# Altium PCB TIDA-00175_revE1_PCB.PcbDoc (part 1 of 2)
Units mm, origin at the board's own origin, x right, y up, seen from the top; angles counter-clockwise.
Board outline 109.99 x 49.78 mm, 4 copper layers (Top Layer, mid layer 1-GND, mid layer 2-VCC, Bottom Layer), stack 2.286 mm thick; 124 components, 74 nets, 385 pads, 135 vias.
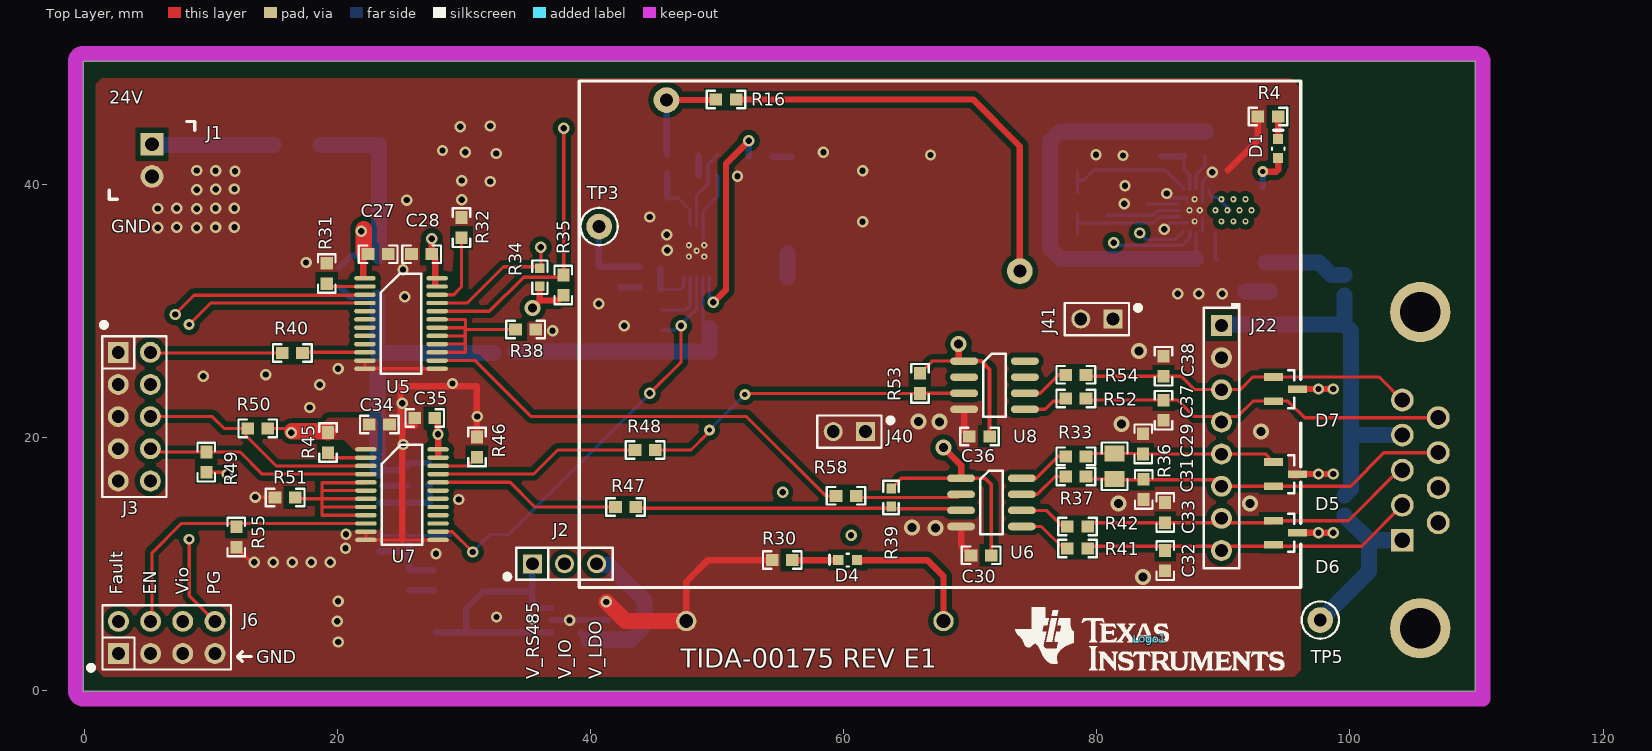
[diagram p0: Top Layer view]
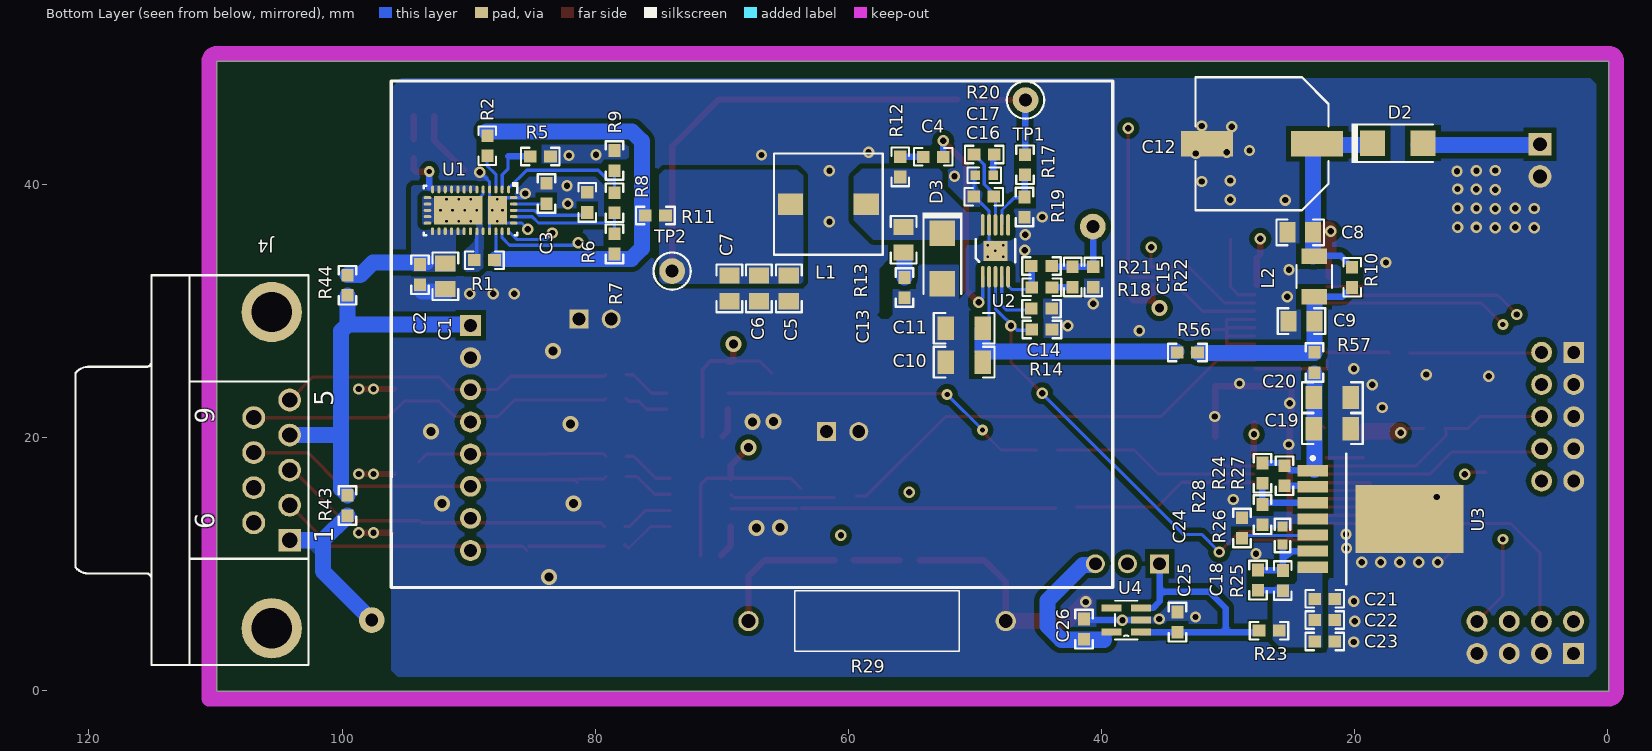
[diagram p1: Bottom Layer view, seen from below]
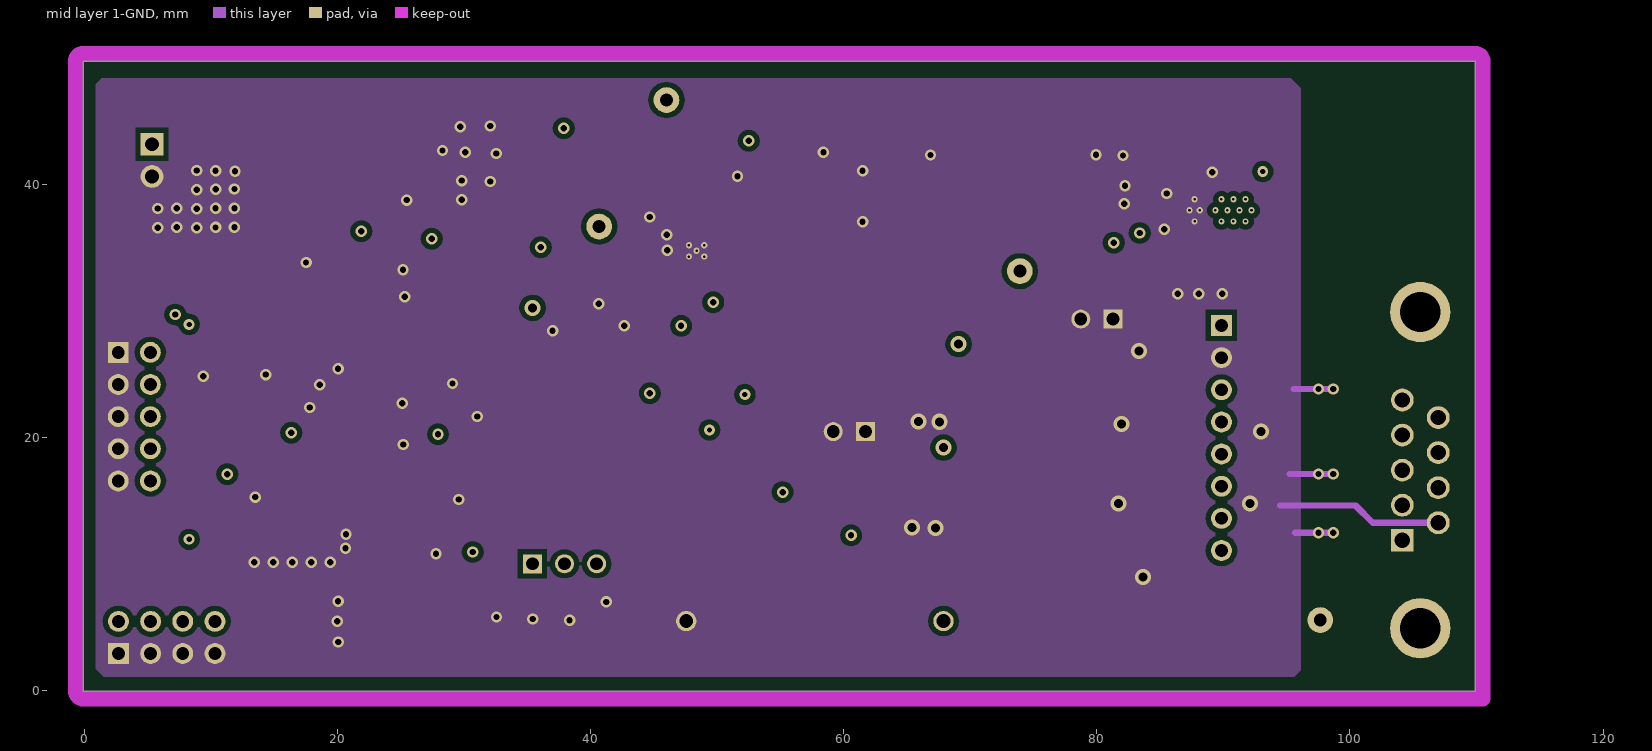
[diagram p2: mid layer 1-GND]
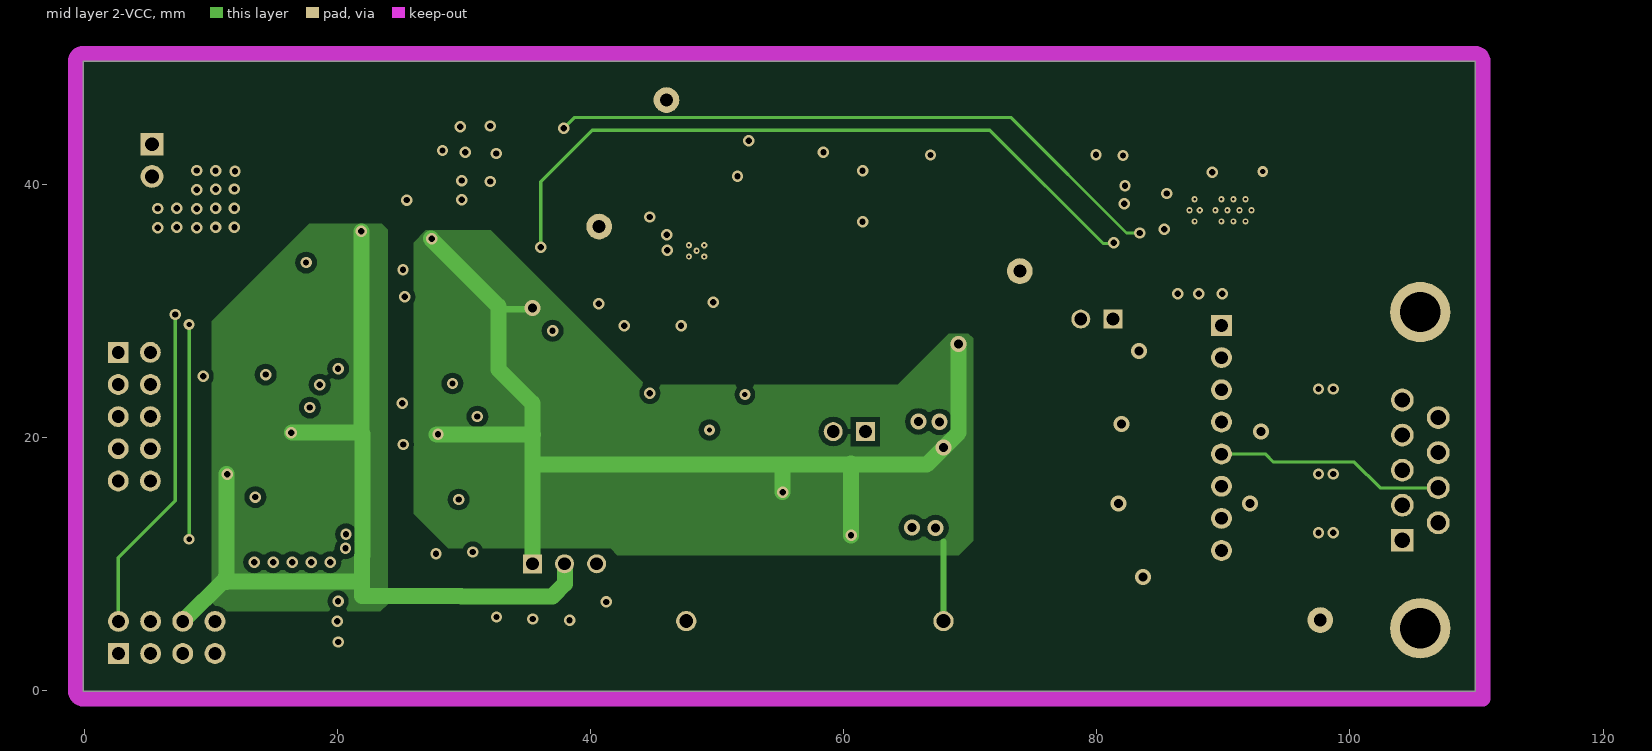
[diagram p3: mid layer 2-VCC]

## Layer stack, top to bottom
Top Layer: signal copper 0.0356
Dielectric: prepreg 1.5037, FR-4, Dk 4.8
mid layer 1-GND: signal copper 0.0356
Dielectric: core 0.32, FR-4, Dk 4.8
mid layer 2-VCC: signal copper 0.0356
Dielectric: prepreg 0.32, FR-4, Dk 4.8
Bottom Layer: signal copper 0.0356

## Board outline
-0.079,-0.068 -0.077,49.714 109.916,49.714 109.916,-0.068

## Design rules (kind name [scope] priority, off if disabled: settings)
AcuteAngle [All] p1: minimum=4.50000000000000E+0001 checktracksonly=FALSE
AssemblyTestPointUsage [All] p1: valid=2
Clearance Clearance_BoardEdge_MountingHoles [OnCopper and InComponentClass('Mounting Holes') vs IsKeepOut] p1: gap=1.016
Clearance Clearance_BoardEdge_Poly [OnCopper and InPoly vs IsKeepOut] p2: gap=0.635
Clearance Clearance_BoardEdge [OnCopper and Not InComponentClass('Logo') and not InComponentClass('FiducialMark') and not InRegion(1000,500,4000,800) and Not IsKeepout vs IsKeepOut] p3: gap=1.905
Clearance Clearance_Poly [InPolygon] p4: gap=0.4
Clearance Clearance_U2 [(ObjectKind = 'Pad') And (Component = 'U2') vs (ObjectKind = 'Pad') And (Component = 'U2')] p5: gap=0.198
Clearance [All] p6: gap=0.203
ComponentClearance ComponentClearance_Shunt [InComponentClass('Header') vs InComponentClass('Shunt')] p1: gap=0 collisioncheckmode=3 verticalgap=0 showdistances=FALSE
ComponentClearance ComponentClearance_Logo [InComponentClass('Logo')] p2: gap=1.27 collisioncheckmode=3 verticalgap=0.254 showdistances=FALSE
ComponentClearance ComponentClearance_ScrewToNut [(HasFootprint('NY PMS 440 0025 PH')) vs (HasFootprint('Keystone_1902C'))] p3: gap=0.127 collisioncheckmode=3 verticalgap=0.254 showdistances=FALSE
ComponentClearance ComponentClearance_MountingHoles [InComponentClass('Mounting Holes')] p4: gap=6.35 collisioncheckmode=3 verticalgap=2540 showdistances=FALSE
ComponentClearance ComponentClearance_SmallPassives [HasFootprint('0201*') or HasFootprint('0402*') or HasFootprint('0508') or HasFootprint('0603*') or HasFootprint('0612') or HasFootprint('0805*') or HasFootprint('0815*') or HasFootprint('0830*') or HasFootprint('1206*') or HasFootprint('1210*') or HasFootprint('1808*') or HasFootprint('1812*') or HasFootprint('1825*') or HasFootprint('2010*') or HasFootprint('2220*') or HasFootprint('2225*') or HasFootprint('2512*') or HasFootprint('2728*') or HasFootprint('3518*') vs HasFootprint('0201*') or HasFootprint('0402*') or HasFootprint('0508') or HasFootprint('0603*') or HasFootprint('0612') or HasFootprint('0805*') or HasFootprint('0815*') or HasFootprint('0830*') or HasFootprint('1206*') or HasFootprint('1210*') or HasFootprint('1808*') or HasFootprint('1812*') or HasFootprint('1825*') or HasFootprint('2010*') or HasFootprint('2220*') or HasFootprint('2225*') or HasFootprint('2512*') or HasFootprint('2728*') or HasFootprint('3518*')] p5: gap=0.508 collisioncheckmode=3 verticalgap=0.254 showdistances=FALSE
ComponentClearance ComponentClearance_THtoSMT [IsThruComponent vs IsSMTComponent] p6: gap=2.54 collisioncheckmode=3 verticalgap=0.762 showdistances=FALSE
ComponentClearance ComponentClearance_THtoTH [IsThruComponent vs IsThruComponent] p7: gap=3 collisioncheckmode=3 verticalgap=0.762 showdistances=FALSE
ComponentClearance [All] p8: gap=1.016 collisioncheckmode=3 verticalgap=0.254 showdistances=FALSE
DiffPairsRouting [All] p1: maxlimit=2.54 minlimit=0.254 mostfreqgap=0.254 maxuncoupledlength=25.4
FabricationTestPointUsage TestPointUsage [All] p1: valid=2 allowmultiple=FALSE
FabricationTestpoint Testpoint [All] p1: side=3 testpointundercomponent=TRUE minsize=1.016 maxsize=2.54 preferedsize=1.524 minholesize=0 maxholesize=1.016 preferedholesize=0.813 testpointgrid=0.025 allowsidetop=TRUE allowsidebottom=TRUE usegrid=TRUE gridtolerance=0
FanoutControl Fanout_LCC [IsLCC] p1: bgadir=Out bgaviamode=Centered fanoutstyle=Auto fanoutdirection=Alternating viagrid=0.025 // Fanout_LCC (Default Rule)
FanoutControl Fanout_BGA [IsBGA] p2: bgadir=Out bgaviamode=Centered fanoutstyle=Auto fanoutdirection=Alternating viagrid=0.025 // Fanout_BGA (Default Rule)
FanoutControl Fanout_Default [All] p4: bgadir=Out bgaviamode=Centered fanoutstyle=Auto fanoutdirection=Alternating viagrid=0.025 // Fanout_Default (Default Rule)
FanoutControl Fanout_Small [(CompPinCount < 5)] p5: bgadir=Out bgaviamode=Centered fanoutstyle=Auto fanoutdirection=OutThenIn viagrid=0.025 // Fanout_Small (Default Rule)
HoleSize HoleSize_CompoentPAD [((Component = U2) or (Component =U1)) and isVia] p1: absolutevalues=TRUE maxlimit=6.375 minlimit=0.2 maxpercent=80.000 minpercent=20.000
HoleSize [All] p2: absolutevalues=TRUE maxlimit=6.375 minlimit=0.203 maxpercent=80.000 minpercent=20.000
MinimumAnnularRing MinimumAnnularRing_ThermalPadVias_U1 [IsVia and (Component = U1)] p1: minimumring=0.099
MinimumAnnularRing MinimumAnnularRing_ThermalPadVias_U2 [IsVia and (Component = U2)] p2: minimumring=0.099
MinimumAnnularRing MinimumAnnularRing_ThermalPadVias [IsVia and InAnyComponent] p3: minimumring=0.15
MinimumAnnularRing [All] p4: minimumring=0.2
MinimumSolderMaskSliver MinimumSolderMaskSliver_ComponentPAD [Component = U2 vs Component = U2] p1: minsoldermaskwidth=0.045
MinimumSolderMaskSliver MinimumSolderMaskSliver_Logo [InComponentClass('Logo') vs InComponentClass('Logo')] p2: minsoldermaskwidth=0.018
MinimumSolderMaskSliver [All] p3: minsoldermaskwidth=0.1
PlaneConnect [All] p1: planeconnectstyle=Relief reliefexpansion=0.254 reliefentries=4 reliefconductorwidth=0.254 reliefairgap=0.254
PolygonConnect [All] p1: connectstyle=Direct reliefconductorwidth=0.254 reliefentries=4 polygonreliefangle="90 Angle" airgapwidth=0.254
RoutingVias ComponentPadVias [IsVia and ((Component = U2) or (Component = U1))] p1: holewidth=0.2 width=0.2 viastyle="Through Hole" minholewidth=0.199 minwidth=0.199 maxholewidth=0.33 maxwidth=0.6
RoutingVias ThermalPadVias [IsVia and InAnyComponent] p2: holewidth=0.2 width=0.5 viastyle="Through Hole" minholewidth=0.3 minwidth=0.5 maxholewidth=0.33 maxwidth=0.6
RoutingVias [All] p3: holewidth=0.406 width=0.864 viastyle="Through Hole" minholewidth=0.3 minwidth=0.66 maxholewidth=1.016 maxwidth=1.651
SMDToCorner SMDToCorner_TPS24750 [InNet(NetR1_1)] p1: distance=18000
SMDToCorner [All] p2: distance=30000
SilkToSilkClearance [All] p1: silktosilkclearance=0.127
SilkscreenOverComponentPads [All] p1: minsilkscreentomaskgap=0.127
SolderMaskExpansion [All] p1: expansion=0.05
Width [All] p1: maxlimit=2.54 minlimit=0.152 preferedwidth=0.254 checkconnectedcopper=TRUE
14 further rules are at their usual default settings.

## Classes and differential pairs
component class Header: J22
component class TIDA-00175_revE1_Block_Diagram: Logo1
component class Logo: Logo1
component class TIDA-00175_revE1_PR: C1 C2 C3 D1 R1 R2 R4 R5 R6 R7 R8 R9 U1
component class TIDA-00175_revE1_PS: C4 C5 C6 C7 C8 C9 C10 C11 C12 C13 C14 C15 C16 C17 C18 C19 C20 C21 C22 C23 C24 C25 C26 D2 D3 D4 J1 J2 L1 L2 R10 R11 R12 R13 R14 R16 R17 R18 R19 R20 R21 R22 R23 R24 R25 R26 R27 R28 R29 R30 R56 R57 TP1 TP2 TP3 U2 U3 U4
component class TIDA-00175_revE1_SC: C27 C28 C29 C30 C31 C32 C33 C34 C35 C36 C37 C38 C43 D5 D6 D7 J3 J4 J6 J22 J40 J41 R31 R32 R33 R34 R35 R36 R37 R38 R39 R40 R41 R42 R43 R44 R45 R46 R47 R48 R49 R50 R51 R52 R53 R54 R55 R58 R63 R73 R74 R76 TP5 U5 U6 U7 U8

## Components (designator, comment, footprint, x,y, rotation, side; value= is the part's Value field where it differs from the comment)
C1 "C2012X5R1E106K125AB" 0805_HV 91.849,32.719 r270 bottom
C2 "C1608X7R1E104K" 0603 93.857,32.842 r270 bottom
C3 "GRM188R71H333KA61D" 0603 83.863,39.26 r270 bottom
C4 "GRM188R61C104KA01D" 0603 53.3,42.153 r0 bottom
C5 "C2012X5R1E106K125AB" 0805_HV 64.706,31.761 r270 bottom
C6 "C2012X5R1E106K125AB" 0805_HV 67.069,31.761 r270 bottom
C7 "C2012X5R1E106K125AB" 0805_HV 69.405,31.761 r270 bottom
C8 "GRM21BR71H105KA12L" 0805_HV 24.304,36.19 r0 bottom
C9 "GRM21BR71H105KA12L" 0805_HV 24.21,29.17 r0 bottom
C10 "GRM31CR61H225KA88L" 1206 50.854,25.936 r0 bottom
C11 "GRM31CR61H225KA88L" 1206 50.854,28.611 r0 bottom
C12 "EEE-FK1J101P" SM_RADIAL_G 27.323,43.186 r0 bottom
C13 "GRM188R60J106ME47D" 0603 55.562,31.825 r270 bottom
C14 "GRM188R71C222KA01D" 0603 44.746,30.155 r180 bottom
C15 "C1608C0G1H100D" 0603 42.283,32.661 r90 bottom
C16 "GRM1885C1H120JA01D" 0603 49.307,39.005 r0 bottom
C17 "GRM188R71H123KA01D" 0603_HV 49.273,40.692 r0 bottom
C18 "GRM188R71C223KA01D" 0603 27.643,8.711 r90 bottom
C19 "GRM31CR61H225KA88L" 1206 21.772,20.668 r180 bottom
C20 "GRM31CR61H225KA88L" 1206 21.771,23.137 r180 bottom
C21 "C1608X5R1A106M" 0603 22.368,7.235 r180 bottom
C22 "C1608X5R1A106M" 0603 22.368,5.551 r180 bottom
C23 "C1608X5R1A106M" 0603 22.368,3.868 r180 bottom
C24 "GRM188R71C333KA01D" 0603 28.898,12.828 r90 bottom
C25 "GRM188R61C104KA01D" 0603 34.004,5.394 r90 bottom
C26 "GRM188R61C104KA01D" 0603 41.386,4.837 r90 bottom
C27 "06033D104KAT2A" 0603 23.226,34.46 r180 top
C28 "06033D104KAT2A" 0603 26.661,34.461 r180 top
C29 "GRM188R71H221KA01D" 0603 83.671,19.475 r270 top
C30 "06033D104KAT2A" 0603 70.866,10.668 r0 top
C31 "GRM188R71H221KA01D" 0603 83.705,15.875 r270 top
C32 "GRM188R71H221KA01D" 0603 85.408,10.25 r90 top
C33 "GRM188R71H221KA01D" 0603 85.408,14.05 r90 top
C34 "06033D104KAT2A" 0603 23.324,21.015 r180 top
C35 "06033D104KAT2A" 0603 26.914,21.515 r180 top
C36 "06033D104KAT2A" 0603 70.739,20.066 r0 top
C37 "GRM188R71H221KA01D" 0603 85.281,22.134 r90 top
C38 "GRM188R71H221KA01D" 0603 85.281,25.611 r90 top
D1 "LG L29K-G2J1-24-Z" "LG L29K_GREEN" 94.335,42.799 r90 top
D2 "MBRA160T3G" SMA 16.602,43.23 r180 bottom
D3 "MBRA160T3G" SMA 52.575,34.114 r270 bottom
D4 "LG L29K-G2J1-24-Z" "LG L29K_GREEN" 60.325,10.296 r180 top
D5 "CDSOT23-SM712" SOT-23 94.917,17.09 r0 top
D6 "CDSOT23-SM712" SOT-23 94.917,12.458 r0 top
D7 "CDSOT23-SM712" SOT-23 94.917,23.807 r0 top
J1 "1725656" CONN_1725656 5.36,41.876 r270 top
J2 "PEC03SAAN" CONN_PEC03SAAN 37.952,10 r0 top
J3 "PEC05DAAN" CONN_PEC05DAAN 3.963,21.628 r270 top
J4 "1734348-1" CONN_1734348-1 115.062,17.399 r90 bottom
J6 "PEC04DAAN" CONN_PEC04DAAN 6.523,4.183 r0 top
J22 "PEC08SAAN" SULLINS_PEC08SAAN 89.854,19.939 r270 top
J40 "PEC02SAAN" CONN_PEC02SAAN 60.452,20.447 r180 top
J41 "PEC02SAAN" CONN_PEC02SAAN 80.01,29.337 r180 top
L1 "7447779182" WE-PD-M 61.582,38.42 r0 bottom
L2 "NLCV32T-4R7M-PFR" NLCV32 23.207,32.694 r270 bottom
Logo1 "Texas Instruments" TI_Stacked_Overlay_Small 84.201,4.064 r0 top
R1 "ERJ-L03KF50MV" 0603 88.762,33.986 r180 bottom
R2 "CRCW060350R0FKEA" 0603 88.528,43.027 r90 bottom
R4 "CRCW06031K00JNEA" 0603 93.535,45.345 r0 top
R5 "CRCW06031K69FKEA" 0603 84.341,42.172 r0 bottom
R6 "CRCW06034K99FKEA" 0603 80.634,38.558 r270 bottom
R7 "CRCW060393K1FKEA" 0603 78.477,35.274 r270 bottom
R8 "CRCW060320K5FKEA" 0603 78.475,38.525 r270 bottom
R9 "RC0603FR-0730KL" 0603 78.475,41.86 r270 bottom
R10 "CRCW060310R0JNEAHP" 0603 20.197,32.636 r270 bottom
R11 "CRCW06030000Z0EA" 0603 75.253,37.524 r0 bottom
R12 "CRCW06030000Z0EA" 0603 55.905,41.358 r270 bottom
R13 "CRCW080510K0JNEA" 0805_HV 55.64,35.597 r90 bottom
R14 "CRCW06034K70JNEA" 0603 44.717,28.502 r180 bottom
R16 "CRCW060351R0JNEA" 0603 50.708,46.689 r180 top
R17 "CRCW060354K9FKEA" 0603 46.04,41.529 r90 bottom
R18 "CRCW06033K90JNEA" 0603 44.715,31.847 r0 bottom
R19 "CRCW060310K0FKEA" 0603 46.093,38.185 r90 bottom
R20 "CRCW060338K3FKEA" 0603 49.273,42.343 r0 bottom
R21 "CRCW0603165KFKEA" 0603 44.748,33.522 r0 bottom
R22 "CRCW060351R0JNEA" 0603 40.658,32.662 r90 bottom
R23 "CRCW06030000Z0EA" 0603 26.767,4.713 r0 bottom
R24 "CRCW060390K9FKEA" 0603 27.28,17.158 r90 bottom
R25 "CRCW060315K4FKEA" 0603 25.679,8.674 r270 bottom
R26 "CRCW06034K99FKEA" 0603_HV 25.708,12.242 r270 bottom
R27 "CRCW060336K5FKEA" 0603 25.551,16.958 r270 bottom
R28 "CRCW060310K0FKEA" 0603 27.293,13.887 r90 bottom
R29 "AC03000001009JAC00" RESAD2032W80L1300D480 57.732,5.473 r0 bottom
R30 "CRCW0603390RJNEA" 0603 55.155,10.296 r0 top
R31 "CRCW06034K70JNEA" 0603 19.168,32.937 r270 top
R32 "CRCW06034K70JNEA" 0603 29.814,36.561 r90 top
R33 "CRCW060310R0JNEAHP" 0603 78.353,18.493 r0 top
R34 "CRCW06034K70JNEA" 0603_HV 36.009,32.644 r90 top
R35 "CRCW06034K70JNEA" 0603 37.854,32.022 r270 top
R36 "ERJ-P06J121V" 0805_HV 81.407,17.705 r90 top
R37 "CRCW060310R0JNEAHP" 0603 78.353,16.889 r0 top
R38 "CRCW06034K70JNEA" 0603 34.878,28.508 r180 top
R39 "CRCW06034K70JNEA" 0603_HV 63.754,15.24 r270 top
R40 "CRCW060322R0JNEA" 0603 16.454,26.652 r0 top
R41 "CRCW060310R0JNEAHP" 0603 78.48,11.207 r0 top
R42 "CRCW060310R0JNEAHP" 0603 78.48,12.951 r0 top
R43 "CRCW06030000Z0EA" 0603 99.568,14.605 r270 bottom
R44 "CRCW06030000Z0EA" 0603 99.568,32.004 r270 bottom
R45 "CRCW06034K70JNEA" 0603 19.27,19.577 r90 top
R46 "CRCW06034K70JNEA" 0603 31.03,19.221 r270 top
R47 "CRCW060322R0JNEA" 0603 42.776,14.487 r0 top
R48 "CRCW060322R0JNEA" 0603 44.323,18.993 r0 top
R49 "CRCW06034K70JNEA" 0603 9.652,18.034 r90 top
R50 "CRCW06034K70JNEA" 0603 13.716,20.701 r180 top
R51 "CRCW06034K70JNEA" 0603 15.882,15.234 r180 top
R52 "CRCW060310R0JNEAHP" 0603 78.353,23.058 r0 top
R53 "CRCW06034K70JNEA" 0603 66.04,24.257 r270 top
R54 "CRCW060310R0JNEAHP" 0603 78.353,24.931 r0 top
R55 "CRCW06034K70JNEA" 0603 12.021,12.116 r90 top
R56 "CRCW06030000Z0EA" 0603 33.22,26.693 r0 bottom
R57 "CRCW06030000Z0EA" 0603 23.168,25.908 r90 bottom
R58 "CRCW060322R0JNEA" 0603 60.198,15.367 r0 top
TP1 "5000" Keystone5000 46.009,46.641 r90 bottom
TP2 "5000" Keystone5000 73.927,33.125 r90 bottom
TP3 "5002" Keystone5002 40.69,36.647 r0 top
TP5 "5000" Keystone5000 97.663,5.559 r0 top
U1 "TPS24750RUV" RUV0036A 89.854,37.923 r270 bottom
U2 "TPS54040ADGQ" DGQ0010D_N 48.384,34.723 r90 bottom
U3 "LMZ14201TZ-ADJ/NOPB" TZA07A_V 17.963,13.545 r180 bottom
U4 "TLV70025DDC" DDC0005A_N 38.052,5.559 r0 bottom
U5 "SN74AVC8T245PW" PW0024A_N 25.035,28.983 r0 top
U6 "SN65HVD77D" D0008A_N 71.685,14.853 r0 top
U7 "SN74AVC8T245PW" PW0024A_N 25.112,15.462 r0 top
U8 "SN65HVD77D" D0008A_N 71.924,24.11 r0 top

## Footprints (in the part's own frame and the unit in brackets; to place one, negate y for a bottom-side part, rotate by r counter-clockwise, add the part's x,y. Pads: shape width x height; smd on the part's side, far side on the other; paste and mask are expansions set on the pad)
0603 [mm] "0603 from SM-752 data"
  rect 1x0.95 smd: 1(-0.8,0) 2(0.8,0)
  silkscreen extent -1.52,-0.69 1.52,0.69, body extent -0.87,-0.47 0.87,0.47, height 0.85
0603_HV [mil] "Ernesto recommended land pattern.  26 mil between pads."
  rect 30x30 smd: 1(-28,0) 2(28,0)
  silkscreen extent -52,-24 52,24, body extent -34,-19 34,19, height 33
0805_HV [mil] "0805 with 30mil clearance between pads"
  rect 50x63 smd: 1(-40,0) 2(40,0)
  silkscreen extent -74,-40 74,40, body extent -43,-29 43,29, height 43
1206 [mm] "1206 from SM-752 data"
  rect 1.3x1.85 smd: 1(-1.45,0) 2(1.45,0)
  silkscreen extent -2.4,-1.21 2.4,1.21, body extent -1.7,-0.9 1.7,0.9, height 1.35
CONN_1725656 [mm] "Phoenix Contact"
  rect 1.8x1.8 hole 1.1: 1(-1.27,0)
  round 1.8 hole 1.1: 2(1.27,0)
  silkscreen extent -3.08,-3.37 3.08,3.37, body extent -2.77,-3.1 2.77,3.1, height 8.52
CONN_1734348-1 [mm] "Connector; D Subminiature 9 Position; Right Angle"
  rect 1.8x1.8 hole 1.2: 1(-5.54,-10.92)
  round 1.8 hole 1.2: 2(-2.77,-10.92) 3(0,-10.92) 4(2.77,-10.92) 5(5.54,-10.92) 6(-4.155,-8.08) 7(-1.385,-8.08) 8(1.385,-8.08) 9(4.155,-8.08)
  round 4.76 hole 3.18: 10(-12.495,-9.5) 11(12.495,-9.5)
  silkscreen extent -15.4,-12.4 15.4,6, body extent -15.4,-12.4 15.4,6.02, height 12.52
CONN_PEC02SAAN [mm] "SULLINS"
  rect 1.5x1.5 hole 1.016: 1(-1.27,0)
  round 1.5 hole 1.016: 2(1.27,0)
  silkscreen extent -3.45,-1.27 2.54,1.27, body extent -2.54,-1.27 2.54,1.27, height 8.38
CONN_PEC03SAAN [mm] "SULLINS"
  rect 1.5x1.5 hole 1.016: 1(-2.54,0)
  round 1.5 hole 1.016: 2(0,0) 3(2.54,0)
  silkscreen extent -4.72,-1.27 3.81,1.27, body extent -3.84,-1.3 3.84,1.3, height 8.38
CONN_PEC04DAAN [mm] "SULLINS"
  rect 1.65x1.65 hole 1.016 mask+0: 1(-3.81,-1.27)
  round 1.65 hole 1.016 mask+0: 2(-3.81,1.27) 3(-1.27,-1.27) 4(-1.27,1.27) 5(1.27,-1.27) 6(1.27,1.27) 7(3.81,-1.27) 8(3.81,1.27)
  silkscreen extent -6.18,-2.6 5.08,2.54, body extent -5.08,-2.54 5.08,2.54, height 8.38
CONN_PEC05DAAN [mm] "SULLINS"
  rect 1.65x1.65 hole 1.016 mask+0: 1(-5.08,-1.27)
  round 1.65 hole 1.016 mask+0: 2(-5.08,1.27) 3(-2.54,-1.27) 4(-2.54,1.27) 5(0,-1.27) 6(0,1.27) 7(2.54,-1.27) 8(2.54,1.27) 9(5.08,-1.27) 10(5.08,1.27)
  silkscreen extent -7.45,-2.6 6.35,2.54, body extent -6.35,-2.54 6.35,2.54, height 8.38
D0008A_N [mm] "SOIC, 8-Leads, Body 4.9x3.9mm, Pitch 1.27mm, IPC Medium Density"
  oval 2.2x0.6 smd: 1(-2.4,1.905) 2(-2.4,0.635) 3(-2.4,-0.635) 4(-2.4,-1.905) 5(2.4,-1.905) 6(2.4,-0.635) 7(2.4,0.635) 8(2.4,1.905)
  silkscreen extent -0.9,-2.5 0.9,2.5, body extent -3,-2.45 3,2.45, height 1.63
DDC0005A_N [mil]
  rect 62x22 smd: 1(-46,37.4) 2(-46,0) 3(-46,-37.4) 4(46,-37.4) 5(46,37.4)
  silkscreen extent -34,-60 34,60, body extent -60,-60 60,60, height 43
DGQ0010D_N [mm] "TSSOP, 10-Leads, Body 3x3mm, Pitch 0.5mm, Thermal Pad 1.88x1.57mm, IPC Medium Density"
  oval 1.7x0.3 smd: 1(-2.05,1) 2(-2.05,0.5) 3(-2.05,0) 4(-2.05,-0.5) 5(-2.05,-1) 6(2.05,-1) 7(2.05,-0.5) 8(2.05,0) 9(2.05,0.5) 10(2.05,1)
  rect 1.57x1.88 smd: 11(0,0)
  silkscreen extent -0.9,-1.55 0.9,1.55, body extent -1.55,-1.55 1.55,1.55, height 1.1
Keystone5000 [mil] "For Keystone 500x miniature loop terminals"
  round 80 hole 40: 1(0,0)
  silkscreen extent -58,-58 58,58, body extent -49,-49 49,49, height 182
Keystone5002 [mil] "For Keystone 500x miniature loop terminals"
  round 80 hole 40: 1(0,0)
  silkscreen extent -58,-58 58,58, body extent -49,-49 49,49, height 182
"LG L29K_GREEN" [mm] "OSRAM"
  rect 0.8x0.8 smd paste-0.4: 1(-0.75,0) 2(0.75,0)
  silkscreen extent -0.1,-0.5 1.45,0.5, body extent -0.9,-0.45 0.9,0.45, height 0.67
NLCV32 [mm] "TDK"
  rect 1.2x2 smd: 1(-1.6,0) 2(1.6,0)
  silkscreen extent -0.9,-1.4 0.9,1.4, body extent -1.7,-1.35 1.7,1.35, height 2.4
PW0024A_N [mm] "TSOP, 24-Leads, Body 7.8x4.4mm, Pitch 0.65mm, IPC Medium Density"
  oval 1.7x0.35 smd: 1(-2.85,3.575) 2(-2.85,2.925) 3(-2.85,2.275) 4(-2.85,1.625) 5(-2.85,0.975) 6(-2.85,0.325) 7(-2.85,-0.325) 8(-2.85,-0.975) 9(-2.85,-1.625) 10(-2.85,-2.275) 11(-2.85,-2.925) 12(-2.85,-3.575) 13(2.85,-3.575) 14(2.85,-2.925) 15(2.85,-2.275) 16(2.85,-1.625) 17(2.85,-0.975) 18(2.85,-0.325) 19(2.85,0.325) 20(2.85,0.975) 21(2.85,1.625) 22(2.85,2.275) 23(2.85,2.925) 24(2.85,3.575)
  silkscreen extent -1.6,-3.95 1.6,3.95, body extent -3.21,-3.9 3.21,3.9, height 0.98
RESAD2032W80L1300D480 [mm] "VISHAY"
  round 1.6 hole 1.1: 1(-10.16,0) 2(10.16,0)
  silkscreen extent -6.5,-2.4 6.5,2.4, body extent -10.57,-2.4 10.57,2.4, height 4.78
RUV0036A [mm]
  oval 0.6x0.24 smd: 1(-1.65,3) 2(-1.65,2.5) 3(-1.65,2) 4(-1.65,1.5) 5(-1.65,1) 6(-1.65,0.5) 7(-1.65,0) 8(-1.65,-0.5) 9(-1.65,-1) 10(-1.65,-1.5) 11(-1.65,-2) 12(-1.65,-2.5) 13(-1.65,-3) 19(1.65,-3) 20(1.65,-2.5) 21(1.65,-2) 22(1.65,-1.5) 23(1.65,-1) 24(1.65,-0.5) 25(1.65,0) 26(1.65,0.5) 27(1.65,1) 28(1.65,1.5) 29(1.65,2) 30(1.65,2.5) 31(1.65,3)
  oval 0.24x0.6 smd: 14(-1,-3.4) 15(-0.5,-3.4) 16(0,-3.4) 17(0.5,-3.4) 18(1,-3.4) 32(1,3.4) 33(0.5,3.4) 34(0,3.4) 35(-0.5,3.4) 36(-1,3.4)
  rect 2.25x1.514 smd paste-1: 37(0,2.118)
  rect 2.25x3.836 smd paste-1.2: 38(0,-0.957)
  silkscreen extent -2.22,-3.7 1.95,3.8, body extent -1.82,-3.57 1.82,3.57, height 1.02
SM_RADIAL_G [mm] "10 x 10.2mm:  Panasonic G"
  rect 4.1x2 smd: 1(-4.35,0) 2(4.35,0)
  silkscreen extent -5.25,-5.25 5.25,5.25, body extent -5.26,-5.26 5.26,5.26, height 10.5
SMA [mm] "Molded Diode, 2-Leads, Body 4.3x2.6mm, IPC Medium Density, based on OnSemi component dimensions and land pattern"
  rect 2x2 smd: 1(-2,0) 2(2,0)
  silkscreen extent -3.66,-1.57 2.79,1.57, body extent -2.6,-1.3 2.6,1.3, height 2.42
SOT-23 [mm] "SOT23, 3-Leads, Body 2.9x1.3mm, Pitch 0.95mm, Lead Span 2.5mm, IPC Medium Density"
  rect 1.5x0.6 smd: 1(-0.95,0.95) 2(-0.95,-0.95) 3(0.95,0)
  silkscreen extent 0.2,-1.5 0.7,1.5, body extent -1.16,-1.45 1.21,1.45, height 1
SULLINS_PEC08SAAN [mm] "SULLINS"
  rect 1.65x1.65 hole 1: 1(-8.89,0)
  round 1.65 hole 1: 2(-6.35,0) 3(-3.81,0) 4(-1.27,0) 5(1.27,0) 6(3.81,0) 7(6.35,0) 8(8.89,0)
  silkscreen extent -10.67,-1.4 10.29,1.52, body extent -10.29,-1.33 10.29,1.33, height 8.38
TI_Stacked_Overlay_Small [mm]
  silkscreen extent -10.63,-2.49 10.63,2.49
TZA07A_V [mm] "D2-PAK, 8-Leads, Body 9.9x10.2mm, Pitch 1.27mm, Lead Span 13.8mm, NSC Recommended"
  rect 2.41x0.89 smd: 1(-5.35,3.81) 2(-5.35,2.54) 3(-5.35,1.27) 4(-5.35,0) 5(-5.35,-1.27) 6(-5.35,-2.54) 7(-5.35,-3.81)
  rect 8.54x5.35 smd: 8(2.28,0)
  silkscreen extent -5.48,-5.15 -2.7,5.15, body extent -2.55,-5.2 7.55,5.2, height 4.67
WE-PD-M [mm] "Wurth Elektronik recommended land pattern, 2008-01-04"
  rect 2x1.7 smd: 1(-3,0) 2(3,0)
  silkscreen extent -4.3,-4 4.3,4, body extent -3.81,-3.84 3.81,3.79, height 4.5

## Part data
C1 C5 C6 C7: "CAP, CERM, 10uF, 25V, +/-10%, X5R, 0805"
C2: "CAP, CERM, 0.1uF, 25V, +/-10%, X7R, 0603"
C3: "CAP, CERM, 0.033uF, 50V, +/-10%, X7R, 0603"
C4 C25 C26: "CAP, CERM, 0.1uF, 16V, +/-10%, X5R, 0603"
C8 C9: "CAP, CERM, 1uF, 50V, +/-10%, X7R, 0805"
C10 C11 C19 C20: "CAP, CERM, 2.2uF, 50V, +/-10%, X5R, 1206"
C12: "CAP, AL, 100uF, 63V, +/-20%, 0.35 ohm, SMD"
C13: "CAP, CERM, 10uF, 6.3V, +/-20%, X5R, 0603"
C14: "CAP, CERM, 2200pF, 16V, +/-10%, X7R, 0603"
C15: "CAP, CERM, 10pF, 50V, +/-5%, C0G/NP0, 0603"
C16: "CAP, CERM, 12pF, 50V, +/-5%, C0G/NP0, 0603"
C17: "CAP, CERM, 0.012uF, 50V, +/-10%, X7R, 0603"
C18: "CAP, CERM, 0.022uF, 16V, +/-10%, X7R, 0603"
C21 C22 C23: "CAP, CERM, 10uF, 10V, +/-20%, X5R, 0603"
C24: "CAP, CERM, 0.033uF, 16V, +/-10%, X7R, 0603"
C27 C28 C30 C34 C35 C36: "CAP, CERM, 0.1uF, 25V, +/-10%, X5R, 0603"
C29 C31 C32 C33 C37 C38: "CAP, CERM, 220pF, 50V, +/-10%, X7R, 0603"
D1 D4: "LED, Green, SMD"
D2 D3: "Diode, Schottky, 60V, 1A, SMA"
D5 D6 D7: "Diode, TVS, Bi, 7V, 400W, SOT-23"
J1: "Header, 2 Pos, 6A, 63V, TH"
J2: "Header, 100mil, 3x1, Tin plated, TH"
J3: "Header, 100mil, 5x2, Tin plated, TH"
J4: "Conn D-SUB RCPT R/A 9POS GOLD/FL, TH"
J6: "Header, 100mil, 4x2, Tin plated, TH"
J22: "Header, 8x1, 100mil, Tin, TH"
J40 J41: "Header, 100mil, 2x1, Tin plated, TH"
L1: "Inductor, Shielded Drum Core, Ferrite, 82uH, 0.84A, 0.25 ohm, SMD"
L2: "Inductor, Wirewound, Ferrite, 4.7uH, 0.9A, 0.2 ohm, SMD"
Logo1: library part TI_Logo, "Texas Instrument Corporate Signature"
R1: "RES, 0.05 ohm, 1%, 0.1W, 0603"
R2: "RES, 50 ohm, 1%, 0.1W, 0603"
R4: "RES, 1.0k ohm, 5%, 0.1W, 0603"
R5: "RES, 1.69k ohm, 1%, 0.1W, 0603"
R6 R26: "RES, 4.99k ohm, 1%, 0.1W, 0603"
R7: "RES, 93.1k ohm, 1%, 0.1W, 0603"
R8: "RES, 20.5k ohm, 1%, 0.1W, 0603"
R9: "RES, 30.0k ohm, 1%, 0.1W, 0603"
R10 R33 R37 R41 R42 R52 R54: "RES, 10 ohm, 5%, 0.25W, 0603"
R11 R12 R23 R43 R44 R56 R57: "RES, 0 ohm, 5%, 0.1W, 0603"
R13: "RES, 10k ohm, 5%, 0.125W, 0805"
R14 R31 R32 R34 R35 R38 R39 R45 R46 R49 R50 R51 R53 R55: "RES, 4.7k ohm, 5%, 0.1W, 0603"
R16 R22: "RES, 51 ohm, 5%, 0.1W, 0603"
R17: "RES, 54.9k ohm, 1%, 0.1W, 0603"
R18: "RES, 3.9k ohm, 5%, 0.1W, 0603"
R19 R28: "RES, 10.0k ohm, 1%, 0.1W, 0603"
R20: "RES, 38.3k ohm, 1%, 0.1W, 0603"
R21: "RES, 165k ohm, 1%, 0.1W, 0603"
R24: "RES, 90.9k ohm, 1%, 0.1W, 0603"
R25: "RES, 15.4k ohm, 1%, 0.1W, 0603"
R27: "RES, 36.5k ohm, 1%, 0.1W, 0603"
R29: "RES, 10 ohm, 5%, 3W, TH"
R30: "RES, 390 ohm, 5%, 0.1W, 0603"
R36: "RES, 120 ohm, 5%, 0.5W, 0805"
R40 R47 R48 R58: "RES, 22 ohm, 5%, 0.1W, 0603"
TP1 TP2 TP5: "Test Point, Miniature, Red, TH"
TP3: "Test Point, Miniature, White, TH"
U1: "2.5 to 18 V Positive Voltage 10A Integrated Hot-Swap Controller, RUV0036A"
U2: "0.5 A, 42 V Step Down DC/DC Converter with Eco-mode, DGQ0010D"
U3: "1A SIMPLE SWITCHER® Power Module with 42V Maximum Input, 7 pin TO-PMOD"
U4: "200-mA, Low-IQ, LDO Regulator for Portable Devices, DDC0005A"
U5 U7: "8-BIT DUAL-SUPPLY BUS TRANSCEIVER WITH CONFIGURABLE VOLTAGE TRANSLATION AND 3-STATE OUTPUTS, PW0024A"
U6 U8: "3.3-V Full-Duplex RS-485 Transceivers With ±12-kV IEC ESD, D0008A"

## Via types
v1: diameter 0.9, hole 0.5, Top Layer to Bottom Layer, 98 vias
v2: diameter 0.5, hole 0.2, Top Layer to Bottom Layer, 19 vias
v3: diameter 1.27, hole 0.711, Top Layer to Bottom Layer, 13 vias
v4: diameter 0.864, hole 0.406, Top Layer to Bottom Layer, 5 vias

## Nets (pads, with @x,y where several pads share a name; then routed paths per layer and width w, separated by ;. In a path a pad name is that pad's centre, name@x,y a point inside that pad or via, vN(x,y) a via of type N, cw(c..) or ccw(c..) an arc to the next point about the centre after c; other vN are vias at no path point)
ENC_OC_FAULT: R34.2 U1.30 U5.21 | length 73.6
  Top Layer w0.254: U5.21@27.885,30.608 30.277,30.608 33.133,33.464 36.098,33.464 v1@36.098,34.834
  mid layer 2-VCC w0.254: v1@36.075,34.935 36.075,36.607 36.073,36.609 36.073,40.199 40.131,44.257 71.562,44.257 80.513,35.306 81.18,35.306 v1@81.352,35.478
  Bottom Layer w0.254: v1@81.307,35.252 81.386,35.173 86.774,35.173 87.365,35.764 U1.30@87.365,36.233
  other v1: 36.073,35.008 81.352,35.377
ENC_PG: R35.1 U1.31 U5.20 | length 76.7
  Top Layer w0.254: U5.20@27.91,29.946 32.018,29.946 34.716,32.644 37.677,32.644 R35.1@37.854,32.822 ; v1@37.73,44.573 v1(37.892,44.411) 37.892,32.886 R35.1@37.818,32.812
  mid layer 2-VCC w0.254: v1(37.892,44.411) 38.746,45.265 73.222,45.265 82.352,36.135 83.217,36.135 v1@83.398,36.315
  Bottom Layer w0.254: v1@83.376,36.113 83.859,35.63 86.212,35.63 U1.31@86.854,36.273
  other v1: 83.398,36.135
ENC_PWR_ENABLE: R14.1 U2.3 U7.14 | length 34.7
  Top Layer w0.254: U7.14@27.962,12.537 29.098,12.537 v1(30.704,10.932) ; v1(44.7,23.48) 47.162,25.942 v1(47.162,28.796)
  mid layer 2-VCC w0.254: v1@44.823,23.312 v1@44.823,23.337
  Bottom Layer w0.254: v1(30.704,10.932) 32.097,12.325 33.555,12.325 v1@44.521,23.292 ; R14.1@45.642,28.444 46.678,28.444 48.384,30.151 U2.3@48.384,32.673
GND_ENC: C1.2 C2.2 C3.1 C5.2 C6.2 C7.2 C8.2 C9.2 C10.2 C11.2 C12.2 C13.2 C14.2 C16.2 C17.2 C19.2 C20.2 C21.2 C22.2 C23.2 C24.2 C25.2 C26.2 C27.1 C28.2 C29.1 C30.1 C31.2 C32.1 C33.2 C34.1 C35.2 C36.1 C37.1 C38.2 D3.2 D5.3 D6.3 D7.3 J1.2 J3.1 J3.3 J3.5 J3.7 J3.9 J4.6 J6.1 J6.3 J6.5 J6.7 J22.2 J40.1 J40.2 J41.1 J41.2 R4.1 R5.1 R6.1 R9.1 R14.2 R19.1 R22.1 R26.1 R28.1 R29.1 R30.1 R31.1 R32.2 R38.1 R46.1 R51.2 R55.1 U1.4 U1.28 U1.32 U1.36 U1.37 U2.9 U2.11 U3.4 U3.8 U4.2 U5.11 U5.12 U5.13 U6.4 U7.11 U7.12 U7.13 U8.4 | length 116.3
  Top Layer w0.254: R55.1@12.021,11.316 13.207,10.13 v1(13.437,10.13) ; v1(13.528,15.272) R51.2@15.044,15.272 ; R51.2@15.044,15.024 R51.2@15.082,14.986 ; U5.11@22.185,26.058 U5.12@22.185,25.408 U5.13@27.885,25.408 ; U7.11@22.262,12.537 U7.12@22.262,11.887 25.111,11.887 U7.13@27.962,11.887
  Top Layer w0.508: 25.111,11.887 25.138,11.914 25.138,20.898 ; 26.115,20.898 25.138,20.898 ; R46.1@31.03,20.021 31.03,24.044 24.994,24.044 24.994,21.041 25.138,20.898 ; R29.1@47.572,5.473 47.572,8.583 49.285,10.296 R30.1@54.355,10.296 ; U6.4@69.285,12.948 69.285,11.449 C30.1@70.066,10.668 ; U8.4@69.524,22.205 69.524,20.481 C36.1@69.939,20.066 ; 90.351,41.086 92.735,43.47 R4.1@92.735,45.345 ; D7.3@95.933,23.809 97.525,23.811 v1@98.552,23.812 ; D5.3@95.942,17.093 97.525,17.095 v1@98.552,17.097 ; D6.3@96.129,12.457 v1(97.525,12.461) v1@98.552,12.46
  Top Layer w1.27: v1(41.262,6.987) 42.776,5.473 R29.1@47.572,5.473
  mid layer 1-GND w0.508: 94.488,14.605 100.452,14.605 101.813,13.244 J4.6@106.982,13.244 ; 95.25,17.097 v1(97.525,17.097) v1@98.552,17.097 ; 95.568,23.812 v1(97.525,23.812) v1@98.552,23.812 ; 95.68,12.461 v1(97.525,12.461) v1@98.552,12.461
  Bottom Layer w0.254: U2.11@48.884,35.223 U2.9@48.884,36.773 48.884,37.852 50.073,39.041 50.073,40.603 C17.2@49.984,40.692 ; v1(85.323,36.435) 85.81,36.923 U1.37@87.12,36.923 ; v1@85.476,38.923 U1.37@87.12,38.923 ; U1.37@87.135,38.574 U1.37@87.135,38.609 ; U1.28@88.347,36.266 U1.37@88.347,37.298 ; U1.4@88.354,39.573 88.354,40.201 88.73,40.576 ; U1.37@88.36,38.541 U1.4@88.36,39.573
  Bottom Layer w0.508: U4.2@36.884,5.559 C26.2@41.326,5.559
  Bottom Layer w1.27: C1.2@91.713,31.5 93.677,31.5
  other v1: 20.077,3.821 19.998,5.465 38.353,5.551 35.443,5.638 32.577,5.8 20.063,7.04 14.939,10.13 16.441,10.13 17.943,10.13 19.445,10.13 27.803,10.791 20.654,11.219 20.692,12.331 98.679,12.446 29.584,15.079 98.679,17.097 25.22,19.423 31.07,21.637 17.837,22.347 25.144,22.685 98.679,23.812 18.621,24.154 29.101,24.246 9.402,24.825 14.339,24.95 20.063,25.408 37.01,28.415 42.667,28.798 40.669,30.542 25.331,31.094 86.414,31.338 88.065,31.338 89.905,31.338 25.196,33.232 17.535,33.804 46.066,34.779 46.031,35.999 8.892,36.541 5.828,36.558 10.383,36.576 7.32,36.593 11.875,36.593 61.5,37.02 44.7,37.401 8.892,38.052 5.828,38.069 7.32,38.103 10.383,38.086 11.875,38.103 82.182,38.458 25.495,38.738 29.835,38.769 85.54,39.26 8.9,39.562 10.388,39.596 11.875,39.613 82.235,39.863 32.081,40.209 29.825,40.278 51.622,40.607 89.135,40.928 11.919,41.012 8.9,41.072 10.383,41.062 61.5,41.062 82.078,42.262 66.865,42.299 79.94,42.313 32.568,42.418 30.115,42.518 58.408,42.512 28.317,42.658 29.719,44.535 32.097,44.585
  other v2: 47.784,34.273 48.984,34.273 48.384,34.723 47.784,35.173 48.984,35.173 87.729,37.048 87.329,37.923 88.129,37.923 87.729,38.798
  other v3: 83.655,8.952 67.256,12.831 65.405,12.855 81.711,14.76 92.115,14.76 92.964,20.447 81.962,21.04 67.579,21.221 65.913,21.248 83.352,26.797
NetC3_2: C3.2 U1.35 | length 2.5
  Bottom Layer w0.254: C3.2@84.033,38.423 U1.35@86.505,38.423
NetC4_1: C4.1 U2.1 | length 17.2
  Top Layer w0.508: v1(49.694,30.662) 49.728,30.662 50.711,31.645 50.711,41.617 v1@52.503,43.409
  Bottom Layer w0.254: U2.1@49.384,32.673 49.384,30.955 v1@49.694,30.645
  Bottom Layer w0.508: C4.1@52.5,42.153 v1@52.5,43.297
  other v1: 52.506,43.418
NetC4_2: C4.2 R12.1 | length 1.5
  Bottom Layer w0.508: C4.2@54.402,42.155 R12.1@55.888,42.155
NetC5_1: C5.1 C6.1 C7.1 L1.2 R11.1 R16.1 TP2.1 | length 33.9
  Top Layer w0.508: R16.1@51.405,46.685 70.239,46.685 73.927,42.997 TP2.1@73.927,33.125
NetC8_1: C8.1 C12.1 D2.1 L2.1 R10.1 | length 16.6
  Bottom Layer w0.508: R10.1@20.197,33.436 21.097,34.336 L2.1@23.055,34.336
  Bottom Layer w1.27: D2.1@18.671,43.082 23.283,43.082 L2.1@23.283,34.294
